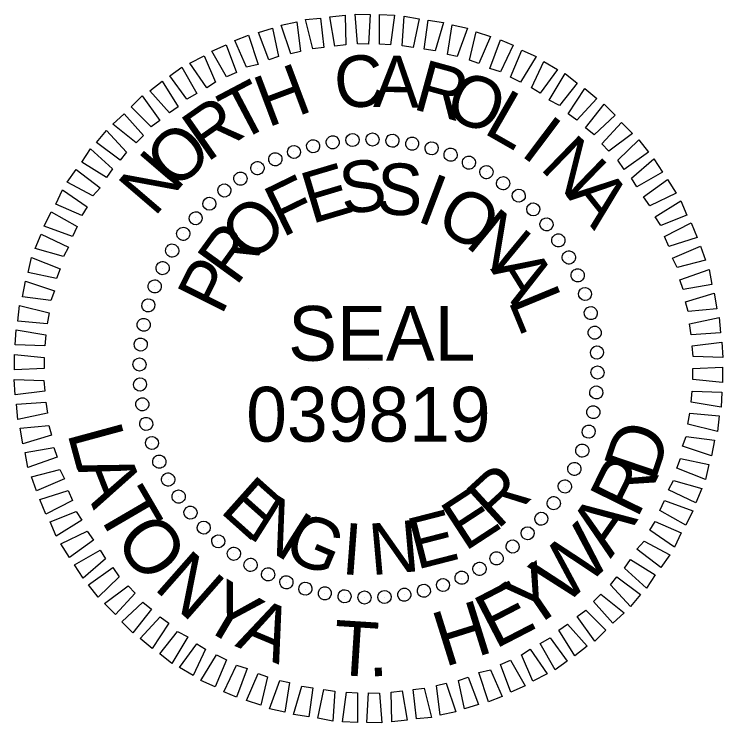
# Model space of a CAD drawing. Extents: x 2241081 to 2251104, y 658534 to 663427.
# Drawn here: x 2249618.9 to 2249696.5, y 660570.7 to 660648.3 of the extents above; entities that cross this region are included whole.
import ezdxf

# ---------------------------------------------------------------- set-up
doc = ezdxf.new("R2010")
doc.units = 0
doc.layers.add('Sheet Professional Seal CELL', color=7, linetype='Continuous')

msp = doc.modelspace()

# ---------------------------------------------------------------- linework, layer by layer
at = {"layer": 'Sheet Professional Seal CELL'}
for p, q in [((2249655.959, 660634.562), (2249655.959, 660634.562)), ((2249658.159, 660634.612), (2249658.159, 660634.612)), ((2249660.359, 660634.462), (2249660.359, 660634.462)), ((2249651.609, 660633.862), (2249651.609, 660633.862)), ((2249653.809, 660634.262), (2249653.809, 660634.262)), ((2249662.509, 660634.112), (2249662.509, 660634.112)), ((2249664.609, 660633.662), (2249664.609, 660633.662)), ((2249649.509, 660633.262), (2249649.509, 660633.262)), ((2249666.709, 660632.962), (2249666.709, 660632.962)), ((2249647.509, 660632.462), (2249647.509, 660632.462)), ((2249645.559, 660631.462), (2249645.559, 660631.462)), ((2249668.709, 660632.062), (2249668.709, 660632.062)), ((2249670.659, 660631.062), (2249670.659, 660631.062)), ((2249643.659, 660630.312), (2249643.659, 660630.312)), ((2249672.459, 660629.812), (2249672.459, 660629.812)), ((2249641.909, 660629.062), (2249641.909, 660629.062)), ((2249674.209, 660628.462), (2249674.209, 660628.462)), ((2249640.259, 660627.562), (2249640.259, 660627.562)), ((2249675.759, 660626.962), (2249675.759, 660626.962)), ((2249638.759, 660626.012), (2249638.759, 660626.012)), ((2249677.259, 660625.312), (2249677.259, 660625.312)), ((2249637.409, 660624.262), (2249637.409, 660624.262)), ((2249678.509, 660623.562), (2249678.509, 660623.562)), ((2249636.159, 660622.462), (2249636.159, 660622.462)), ((2249679.659, 660621.662), (2249679.659, 660621.662)), ((2249635.159, 660620.512), (2249635.159, 660620.512)), ((2249680.659, 660619.712), (2249680.659, 660619.712)), ((2249634.259, 660618.512), (2249634.259, 660618.512)), ((2249681.459, 660617.712), (2249681.459, 660617.712)), ((2249633.559, 660616.412), (2249633.559, 660616.412)), ((2249682.059, 660615.612), (2249682.059, 660615.612)), ((2249633.109, 660614.312), (2249633.109, 660614.312)), ((2249682.459, 660613.412), (2249682.459, 660613.412)), ((2249632.759, 660612.162), (2249632.759, 660612.162)), ((2249682.759, 660611.262), (2249682.759, 660611.262)), ((2249632.609, 660609.962), (2249632.609, 660609.962)), ((2249657.709, 660609.512), (2249657.709, 660609.512)), ((2249682.809, 660609.062), (2249682.809, 660609.062)), ((2249632.659, 660607.762), (2249632.659, 660607.762)), ((2249682.659, 660606.862), (2249682.659, 660606.862)), ((2249632.959, 660605.612), (2249632.959, 660605.612)), ((2249682.309, 660604.712), (2249682.309, 660604.712)), ((2249633.359, 660603.412), (2249633.359, 660603.412)), ((2249681.859, 660602.612), (2249681.859, 660602.612)), ((2249633.959, 660601.312), (2249633.959, 660601.312)), ((2249681.159, 660600.512), (2249681.159, 660600.512)), ((2249634.759, 660599.312), (2249634.759, 660599.312)), ((2249680.259, 660598.512), (2249680.259, 660598.512)), ((2249635.759, 660597.362), (2249635.759, 660597.362)), ((2249679.259, 660596.562), (2249679.259, 660596.562)), ((2249636.909, 660595.462), (2249636.909, 660595.462)), ((2249678.009, 660594.762), (2249678.009, 660594.762)), ((2249638.159, 660593.712), (2249638.159, 660593.712)), ((2249676.659, 660593.012), (2249676.659, 660593.012)), ((2249639.659, 660592.062), (2249639.659, 660592.062)), ((2249675.159, 660591.462), (2249675.159, 660591.462)), ((2249641.209, 660590.562), (2249641.209, 660590.562)), ((2249673.509, 660589.962), (2249673.509, 660589.962)), ((2249642.959, 660589.212), (2249642.959, 660589.212)), ((2249671.759, 660588.712), (2249671.759, 660588.712)), ((2249644.759, 660587.962), (2249644.759, 660587.962)), ((2249669.859, 660587.562), (2249669.859, 660587.562)), ((2249646.709, 660586.962), (2249646.709, 660586.962)), ((2249667.909, 660586.562), (2249667.909, 660586.562)), ((2249648.709, 660586.062), (2249648.709, 660586.062)), ((2249665.909, 660585.762), (2249665.909, 660585.762)), ((2249650.809, 660585.362), (2249650.809, 660585.362)), ((2249652.909, 660584.912), (2249652.909, 660584.912)), ((2249663.809, 660585.162), (2249663.809, 660585.162)), ((2249655.059, 660584.562), (2249655.059, 660584.562)), ((2249657.259, 660584.412), (2249657.259, 660584.412)), ((2249659.459, 660584.462), (2249659.459, 660584.462)), ((2249661.609, 660584.762), (2249661.609, 660584.762))]:
    msp.add_line(p, q, dxfattribs=at)
for points in [[(2249651.609, 660644.512), (2249650.809, 660647.712), (2249652.459, 660647.862), (2249652.809, 660644.662)], [(2249654.009, 660644.812), (2249653.459, 660648.012), (2249655.159, 660648.212), (2249655.209, 660644.962)], [(2249656.509, 660645.062), (2249656.259, 660648.312), (2249657.909, 660648.262), (2249657.709, 660645.012)], [(2249658.909, 660645.012), (2249658.909, 660648.262), (2249660.559, 660648.212), (2249660.109, 660644.962)], [(2249661.409, 660644.862), (2249661.609, 660648.112), (2249663.259, 660647.812), (2249662.609, 660644.662)], [(2249663.809, 660644.462), (2249664.259, 660647.662), (2249665.909, 660647.412), (2249665.009, 660644.312)], [(2249649.209, 660643.962), (2249648.159, 660647.112), (2249649.859, 660647.462), (2249650.259, 660644.212)], [(2249666.359, 660643.912), (2249666.859, 660647.162), (2249668.559, 660646.762), (2249667.409, 660643.662)], [(2249646.809, 660643.312), (2249645.659, 660646.312), (2249647.209, 660646.762), (2249647.859, 660643.662)], [(2249668.759, 660643.262), (2249669.509, 660646.362), (2249671.059, 660645.862), (2249669.809, 660642.912)], [(2249644.359, 660642.512), (2249643.059, 660645.412), (2249644.559, 660646.012), (2249645.609, 660642.812)], [(2249671.009, 660642.362), (2249672.159, 660645.512), (2249673.559, 660644.912), (2249672.159, 660642.012)], [(2249642.159, 660641.462), (2249640.559, 660644.262), (2249642.109, 660644.962), (2249643.259, 660641.912)], [(2249640.009, 660640.262), (2249638.159, 660642.962), (2249639.709, 660643.762), (2249640.959, 660640.862)], [(2249673.259, 660641.412), (2249674.509, 660644.362), (2249676.059, 660643.662), (2249674.359, 660640.862)], [(2249675.559, 660640.262), (2249676.909, 660643.112), (2249678.409, 660642.262), (2249676.509, 660639.662)], [(2249637.809, 660639.012), (2249635.959, 660641.562), (2249637.259, 660642.512), (2249638.909, 660639.612)], [(2249677.509, 660638.912), (2249679.259, 660641.812), (2249680.559, 660640.762), (2249678.609, 660638.312)], [(2249635.909, 660637.512), (2249633.759, 660639.912), (2249635.109, 660640.962), (2249636.859, 660638.162)], [(2249679.559, 660637.412), (2249681.409, 660640.162), (2249682.709, 660639.062), (2249680.509, 660636.712)], [(2249633.909, 660635.962), (2249631.709, 660638.162), (2249632.909, 660639.362), (2249634.859, 660636.662)], [(2249681.459, 660635.862), (2249683.509, 660638.462), (2249684.709, 660637.262), (2249682.409, 660635.112)], [(2249632.259, 660634.212), (2249629.709, 660636.262), (2249630.959, 660637.412), (2249633.059, 660635.012)], [(2249683.259, 660634.112), (2249685.409, 660636.462), (2249686.609, 660635.262), (2249684.009, 660633.312)], [(2249630.509, 660632.312), (2249627.909, 660634.262), (2249629.009, 660635.562), (2249631.209, 660633.212)], [(2249685.009, 660632.312), (2249687.309, 660634.562), (2249688.359, 660633.212), (2249685.709, 660631.312)], [(2249629.009, 660630.412), (2249626.309, 660632.112), (2249627.259, 660633.562), (2249629.659, 660631.362)], [(2249686.509, 660630.362), (2249688.959, 660632.462), (2249689.909, 660631.012), (2249687.109, 660629.412)], [(2249627.509, 660628.412), (2249624.709, 660629.912), (2249625.709, 660631.312), (2249628.309, 660629.312)], [(2249687.809, 660628.312), (2249690.459, 660630.212), (2249691.409, 660628.712), (2249688.509, 660627.312)], [(2249626.309, 660626.262), (2249623.459, 660627.512), (2249624.209, 660629.062), (2249626.909, 660627.212)], [(2249689.109, 660626.112), (2249691.909, 660627.862), (2249692.559, 660626.312), (2249689.709, 660625.162)], [(2249625.309, 660623.962), (2249622.209, 660625.112), (2249622.959, 660626.662), (2249625.809, 660625.062)], [(2249690.109, 660623.962), (2249693.059, 660625.462), (2249693.709, 660623.862), (2249690.609, 660622.862)], [(2249624.309, 660621.762), (2249621.209, 660622.662), (2249621.859, 660624.212), (2249624.859, 660622.812)], [(2249691.009, 660621.612), (2249694.059, 660622.912), (2249694.609, 660621.362), (2249691.509, 660620.562)], [(2249623.559, 660619.362), (2249620.459, 660620.012), (2249620.809, 660621.662), (2249623.959, 660620.412)], [(2249691.809, 660619.212), (2249695.009, 660620.362), (2249695.309, 660618.712), (2249692.159, 660618.162)], [(2249622.909, 660616.962), (2249619.809, 660617.362), (2249620.159, 660619.062), (2249623.309, 660618.012)], [(2249692.409, 660616.812), (2249695.559, 660617.762), (2249695.859, 660616.062), (2249692.709, 660615.762)], [(2249622.509, 660614.412), (2249619.309, 660614.712), (2249619.509, 660616.412), (2249622.759, 660615.612)], [(2249692.859, 660614.412), (2249696.109, 660615.112), (2249696.259, 660613.412), (2249693.059, 660613.212)], [(2249622.259, 660612.012), (2249619.009, 660612.112), (2249619.109, 660613.762), (2249622.359, 660613.212)], [(2249693.159, 660612.012), (2249696.409, 660612.412), (2249696.509, 660610.712), (2249693.259, 660610.812)], [(2249622.209, 660609.512), (2249618.959, 660609.362), (2249618.959, 660611.062), (2249622.209, 660610.712)], [(2249693.209, 660609.512), (2249696.459, 660609.662), (2249696.459, 660607.962), (2249693.209, 660608.312)], [(2249622.259, 660607.012), (2249619.009, 660606.612), (2249618.909, 660608.312), (2249622.159, 660608.212)], [(2249693.159, 660607.012), (2249696.409, 660606.912), (2249696.309, 660605.262), (2249693.059, 660605.812)], [(2249622.559, 660604.612), (2249619.309, 660603.912), (2249619.159, 660605.612), (2249622.359, 660605.812)], [(2249692.909, 660604.612), (2249696.109, 660604.312), (2249695.909, 660602.612), (2249692.659, 660603.412)], [(2249623.009, 660602.212), (2249619.859, 660601.262), (2249619.559, 660602.962), (2249622.709, 660603.262)], [(2249692.509, 660602.062), (2249695.609, 660601.662), (2249695.259, 660599.962), (2249692.109, 660601.012)], [(2249623.609, 660599.812), (2249620.409, 660598.662), (2249620.109, 660600.312), (2249623.259, 660600.862)], [(2249691.859, 660599.662), (2249694.959, 660599.012), (2249694.609, 660597.362), (2249691.459, 660598.612)], [(2249624.409, 660597.412), (2249621.359, 660596.112), (2249620.809, 660597.662), (2249623.909, 660598.462)], [(2249691.109, 660597.262), (2249694.209, 660596.362), (2249693.559, 660594.812), (2249690.559, 660596.212)], [(2249625.309, 660595.062), (2249622.359, 660593.562), (2249621.709, 660595.162), (2249624.809, 660596.162)], [(2249690.109, 660595.062), (2249693.209, 660593.912), (2249692.459, 660592.362), (2249689.609, 660593.962)], [(2249626.309, 660592.912), (2249623.509, 660591.162), (2249622.859, 660592.712), (2249625.709, 660593.862)], [(2249689.109, 660592.762), (2249691.959, 660591.512), (2249691.209, 660589.962), (2249688.509, 660591.812)], [(2249627.609, 660590.712), (2249624.959, 660588.812), (2249624.009, 660590.312), (2249626.909, 660591.712)], [(2249687.909, 660590.612), (2249690.709, 660589.112), (2249689.709, 660587.712), (2249687.109, 660589.712)], [(2249628.909, 660588.662), (2249626.459, 660586.562), (2249625.509, 660588.012), (2249628.309, 660589.612)], [(2249686.409, 660588.612), (2249689.109, 660586.912), (2249688.159, 660585.462), (2249685.759, 660587.662)], [(2249630.409, 660586.712), (2249628.109, 660584.462), (2249627.059, 660585.812), (2249629.709, 660587.712)], [(2249684.909, 660586.712), (2249687.509, 660584.762), (2249686.409, 660583.462), (2249684.209, 660585.812)], [(2249632.159, 660584.912), (2249630.009, 660582.562), (2249628.809, 660583.762), (2249631.409, 660585.712)], [(2249683.159, 660584.812), (2249685.709, 660582.762), (2249684.459, 660581.612), (2249682.359, 660584.012)], [(2249633.959, 660583.162), (2249631.909, 660580.562), (2249630.709, 660581.762), (2249633.009, 660583.912)], [(2249681.509, 660583.062), (2249683.709, 660580.862), (2249682.509, 660579.662), (2249680.559, 660582.362)], [(2249635.859, 660581.612), (2249634.009, 660578.862), (2249632.709, 660579.962), (2249634.909, 660582.312)], [(2249679.509, 660581.512), (2249681.659, 660579.112), (2249680.309, 660578.062), (2249678.559, 660580.862)], [(2249637.909, 660580.112), (2249636.159, 660577.212), (2249634.859, 660578.262), (2249636.809, 660580.712)], [(2249639.859, 660578.762), (2249638.509, 660575.912), (2249637.009, 660576.762), (2249638.909, 660579.362)], [(2249677.609, 660580.012), (2249679.459, 660577.462), (2249678.159, 660576.512), (2249676.509, 660579.412)], [(2249675.409, 660578.762), (2249677.259, 660576.062), (2249675.709, 660575.262), (2249674.459, 660578.162)], [(2249642.159, 660577.612), (2249640.909, 660574.662), (2249639.359, 660575.362), (2249641.059, 660578.162)], [(2249644.409, 660576.662), (2249643.259, 660573.512), (2249641.859, 660574.112), (2249643.259, 660577.012)], [(2249673.259, 660577.562), (2249674.859, 660574.762), (2249673.309, 660574.062), (2249672.159, 660577.112)], [(2249671.059, 660576.512), (2249672.359, 660573.612), (2249670.859, 660573.012), (2249669.809, 660576.212)], [(2249646.659, 660575.762), (2249645.909, 660572.662), (2249644.359, 660573.162), (2249645.609, 660576.112)], [(2249668.609, 660575.712), (2249669.759, 660572.712), (2249668.209, 660572.262), (2249667.559, 660575.362)], [(2249649.059, 660575.112), (2249648.559, 660571.862), (2249646.859, 660572.262), (2249648.009, 660575.362)], [(2249651.609, 660574.562), (2249651.159, 660571.362), (2249649.509, 660571.612), (2249650.409, 660574.712)], [(2249666.209, 660575.062), (2249667.259, 660571.912), (2249665.559, 660571.562), (2249665.159, 660574.812)], [(2249654.009, 660574.162), (2249653.809, 660570.912), (2249652.159, 660571.212), (2249652.809, 660574.362)], [(2249656.509, 660574.012), (2249656.509, 660570.762), (2249654.859, 660570.812), (2249655.309, 660574.062)], [(2249658.909, 660573.962), (2249659.159, 660570.712), (2249657.509, 660570.762), (2249657.709, 660574.012)], [(2249661.409, 660574.212), (2249661.959, 660571.012), (2249660.259, 660570.812), (2249660.209, 660574.062)], [(2249663.809, 660574.512), (2249664.609, 660571.312), (2249662.959, 660571.162), (2249662.609, 660574.362)]]:
    msp.add_lwpolyline(points, close=True, dxfattribs=at)
for centre, major_axis in [((2249655.959, 660634.531), (-0.05, 0.718)), ((2249658.147, 660634.588), (0.013, 0.72)), ((2249660.33, 660634.455), (0.075, 0.716)), ((2249651.642, 660633.847), (-0.174, 0.699)), ((2249653.786, 660634.283), (-0.113, 0.711)), ((2249662.494, 660634.131), (0.137, 0.707)), ((2249649.544, 660633.226), (-0.234, 0.681)), ((2249664.622, 660633.621), (0.198, 0.692)), ((2249666.697, 660632.926), (0.258, 0.672)), ((2249647.508, 660632.424), (-0.293, 0.658)), ((2249645.55, 660631.448), (-0.349, 0.63)), ((2249668.703, 660632.054), (0.316, 0.647)), ((2249670.626, 660631.01), (0.371, 0.617)), ((2249643.684, 660630.304), (-0.403, 0.597)), ((2249672.451, 660629.802), (0.423, 0.582)), ((2249641.926, 660629.003), (-0.453, 0.56)), ((2249674.163, 660628.44), (0.472, 0.543)), ((2249640.287, 660627.553), (-0.5, 0.518)), ((2249675.75, 660626.934), (0.518, 0.5)), ((2249638.781, 660625.966), (-0.543, 0.472)), ((2249677.2, 660625.295), (0.56, 0.453)), ((2249637.419, 660624.254), (-0.582, 0.423)), ((2249678.501, 660623.537), (0.597, 0.403)), ((2249636.211, 660622.429), (-0.617, 0.371)), ((2249679.644, 660621.671), (0.63, 0.349)), ((2249635.167, 660620.506), (-0.647, 0.316)), ((2249680.621, 660619.713), (0.658, 0.293)), ((2249634.295, 660618.5), (-0.672, 0.258)), ((2249681.422, 660617.677), (0.681, 0.234)), ((2249633.6, 660616.425), (-0.692, 0.198)), ((2249682.044, 660615.579), (0.699, 0.174)), ((2249633.09, 660614.298), (-0.707, 0.137)), ((2249682.48, 660613.435), (0.711, 0.113)), ((2249632.766, 660612.134), (-0.716, 0.075)), ((2249682.728, 660611.262), (0.718, 0.05)), ((2249632.633, 660609.95), (-0.72, 0.013)), ((2249682.785, 660609.074), (0.72, -0.013)), ((2249632.69, 660607.763), (-0.718, -0.05)), ((2249682.651, 660606.89), (0.716, -0.075)), ((2249632.938, 660605.589), (-0.711, -0.113)), ((2249682.328, 660604.727), (0.707, -0.137)), ((2249633.374, 660603.445), (-0.699, -0.174)), ((2249681.817, 660602.599), (0.692, -0.198)), ((2249633.995, 660601.347), (-0.681, -0.234)), ((2249681.123, 660600.524), (0.672, -0.258)), ((2249634.797, 660599.311), (-0.658, -0.293)), ((2249680.251, 660598.518), (0.647, -0.316)), ((2249635.773, 660597.353), (-0.63, -0.349)), ((2249679.207, 660596.595), (0.617, -0.371)), ((2249636.917, 660595.488), (-0.597, -0.403)), ((2249677.999, 660594.77), (0.582, -0.423)), ((2249638.218, 660593.729), (-0.56, -0.453)), ((2249676.637, 660593.058), (0.543, -0.472)), ((2249639.668, 660592.09), (-0.518, -0.5)), ((2249675.131, 660591.471), (0.5, -0.518)), ((2249641.255, 660590.584), (-0.472, -0.543)), ((2249673.492, 660590.021), (0.453, -0.56)), ((2249642.967, 660589.222), (-0.423, -0.582)), ((2249671.733, 660588.72), (0.403, -0.597)), ((2249644.792, 660588.014), (-0.371, -0.617)), ((2249669.868, 660587.577), (0.349, -0.63)), ((2249646.715, 660586.97), (-0.316, -0.647)), ((2249667.91, 660586.6), (0.293, -0.658)), ((2249648.721, 660586.098), (-0.258, -0.672)), ((2249665.874, 660585.798), (0.234, -0.681)), ((2249650.796, 660585.404), (-0.198, -0.692)), ((2249652.923, 660584.893), (-0.137, -0.707)), ((2249663.776, 660585.177), (0.174, -0.699)), ((2249655.087, 660584.569), (-0.075, -0.716)), ((2249657.271, 660584.436), (-0.013, -0.72)), ((2249659.458, 660584.493), (0.05, -0.718)), ((2249661.632, 660584.741), (0.113, -0.711))]:
    msp.add_ellipse(centre, major_axis=major_axis, ratio=0.999708, dxfattribs=at)

# ---------------------------------------------------------------- texts
for s, height, rotation, p in [('C', 5.638, 6.2198, (2249654.259, 660637.862)), ('A', 5.638, 359.02025, (2249658.209, 660638.162)), ('R', 5.638, 344.62103, (2249662.409, 660637.962)), ('H', 5.638, 20.61941, (2249646.659, 660635.862)), ('O', 5.638, 337.4211, (2249665.759, 660637.212)), ('T', 5.638, 27.81971, (2249643.409, 660634.212)), ('L', 5.638, 330.22081, (2249670.159, 660635.362)), ('R', 5.639, 35.02044, (2249640.009, 660632.012)), ('I', 5.638, 323.02008, (2249674.209, 660632.962)), ('O', 5.639, 42.22168, (2249636.559, 660628.912)), ('N', 5.639, 315.81884, (2249676.359, 660631.412)), ('N', 5.639, 49.42343, (2249634.259, 660626.012)), ('S', 5.638, 7.25554, (2249654.909, 660626.362)), ('E', 5.638, 16.611, (2249651.459, 660625.312)), ('S', 5.638, 357.90033, (2249658.509, 660626.412)), ('F', 5.638, 25.96697, (2249648.259, 660623.812)), ('I', 5.638, 339.18954, (2249662.809, 660625.712)), ('A', 5.639, 308.61709, (2249679.309, 660628.462)), ('O', 5.638, 329.83342, (2249664.809, 660625.012)), ('O', 5.639, 44.68117, (2249644.959, 660620.862)), ('N', 5.639, 320.47655, (2249668.159, 660623.012)), ('R', 5.639, 54.03958, (2249643.209, 660618.412)), ('P', 5.639, 63.39882, (2249641.609, 660615.212)), ('A', 5.639, 301.7602, (2249671.009, 660620.412)), ('L', 5.639, 292.40078, (2249672.959, 660616.962)), ('SEAL', 5.9982, 359.99993, (2249648.91, 660610.361)), ('039819', 5.9982, 359.99993, (2249644.32, 660601.504)), ('L', 5.998, 285.17415, (2249624.7, 660602.472)), ('D', 5.998, 71.22469, (2249689.022, 660596.918)), ('R', 5.998, 63.74443, (2249687.116, 660592.949)), ('A', 5.998, 291.44891, (2249625.668, 660598.906)), ('R', 5.639, 42.48134, (2249671.809, 660591.762)), ('E', 5.638, 318.27682, (2249641.309, 660593.862)), ('T', 5.998, 300.28922, (2249627.678, 660594.108)), ('E', 5.638, 33.12402, (2249668.259, 660589.412)), ('N', 5.639, 327.63389, (2249644.309, 660591.162)), ('A', 5.998, 54.90412, (2249684.221, 660588.626)), ('G', 5.638, 336.99017, (2249648.109, 660588.912)), ('E', 5.638, 14.4117, (2249662.959, 660587.462)), ('O', 5.998, 307.08945, (2249629.713, 660590.661)), ('I', 5.638, 355.70113, (2249654.659, 660587.012)), ('N', 5.638, 5.05632, (2249658.009, 660586.862)), ('W', 5.998, 42.37005, (2249679.057, 660583.37)), ('N', 5.998, 318.64986, (2249634.059, 660585.433)), ('Y', 5.998, 34.45704, (2249675.255, 660580.68)), ('Y', 5.998, 329.37569, (2249638.954, 660581.452)), ('E', 5.998, 27.34771, (2249671.551, 660578.73)), ('H', 5.998, 17.36372, (2249666.005, 660576.797)), ('A', 5.998, 337.28869, (2249642.995, 660579.137)), ('T', 5.998, 356.32935, (2249653.71, 660575.999)), ('.', 5.998, 3.12959, (2249657.706, 660575.761))]:
    msp.add_text(s, height=height, rotation=rotation, dxfattribs=at).set_placement(p)

doc.saveas('drawing.dxf')
